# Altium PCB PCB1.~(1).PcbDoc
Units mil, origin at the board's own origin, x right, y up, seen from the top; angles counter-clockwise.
Board outline 2362.2 x 2362.2 mil, 2 copper layers (Top Layer, Bottom Layer); 62 components, 63 nets, 221 pads, 155 vias.
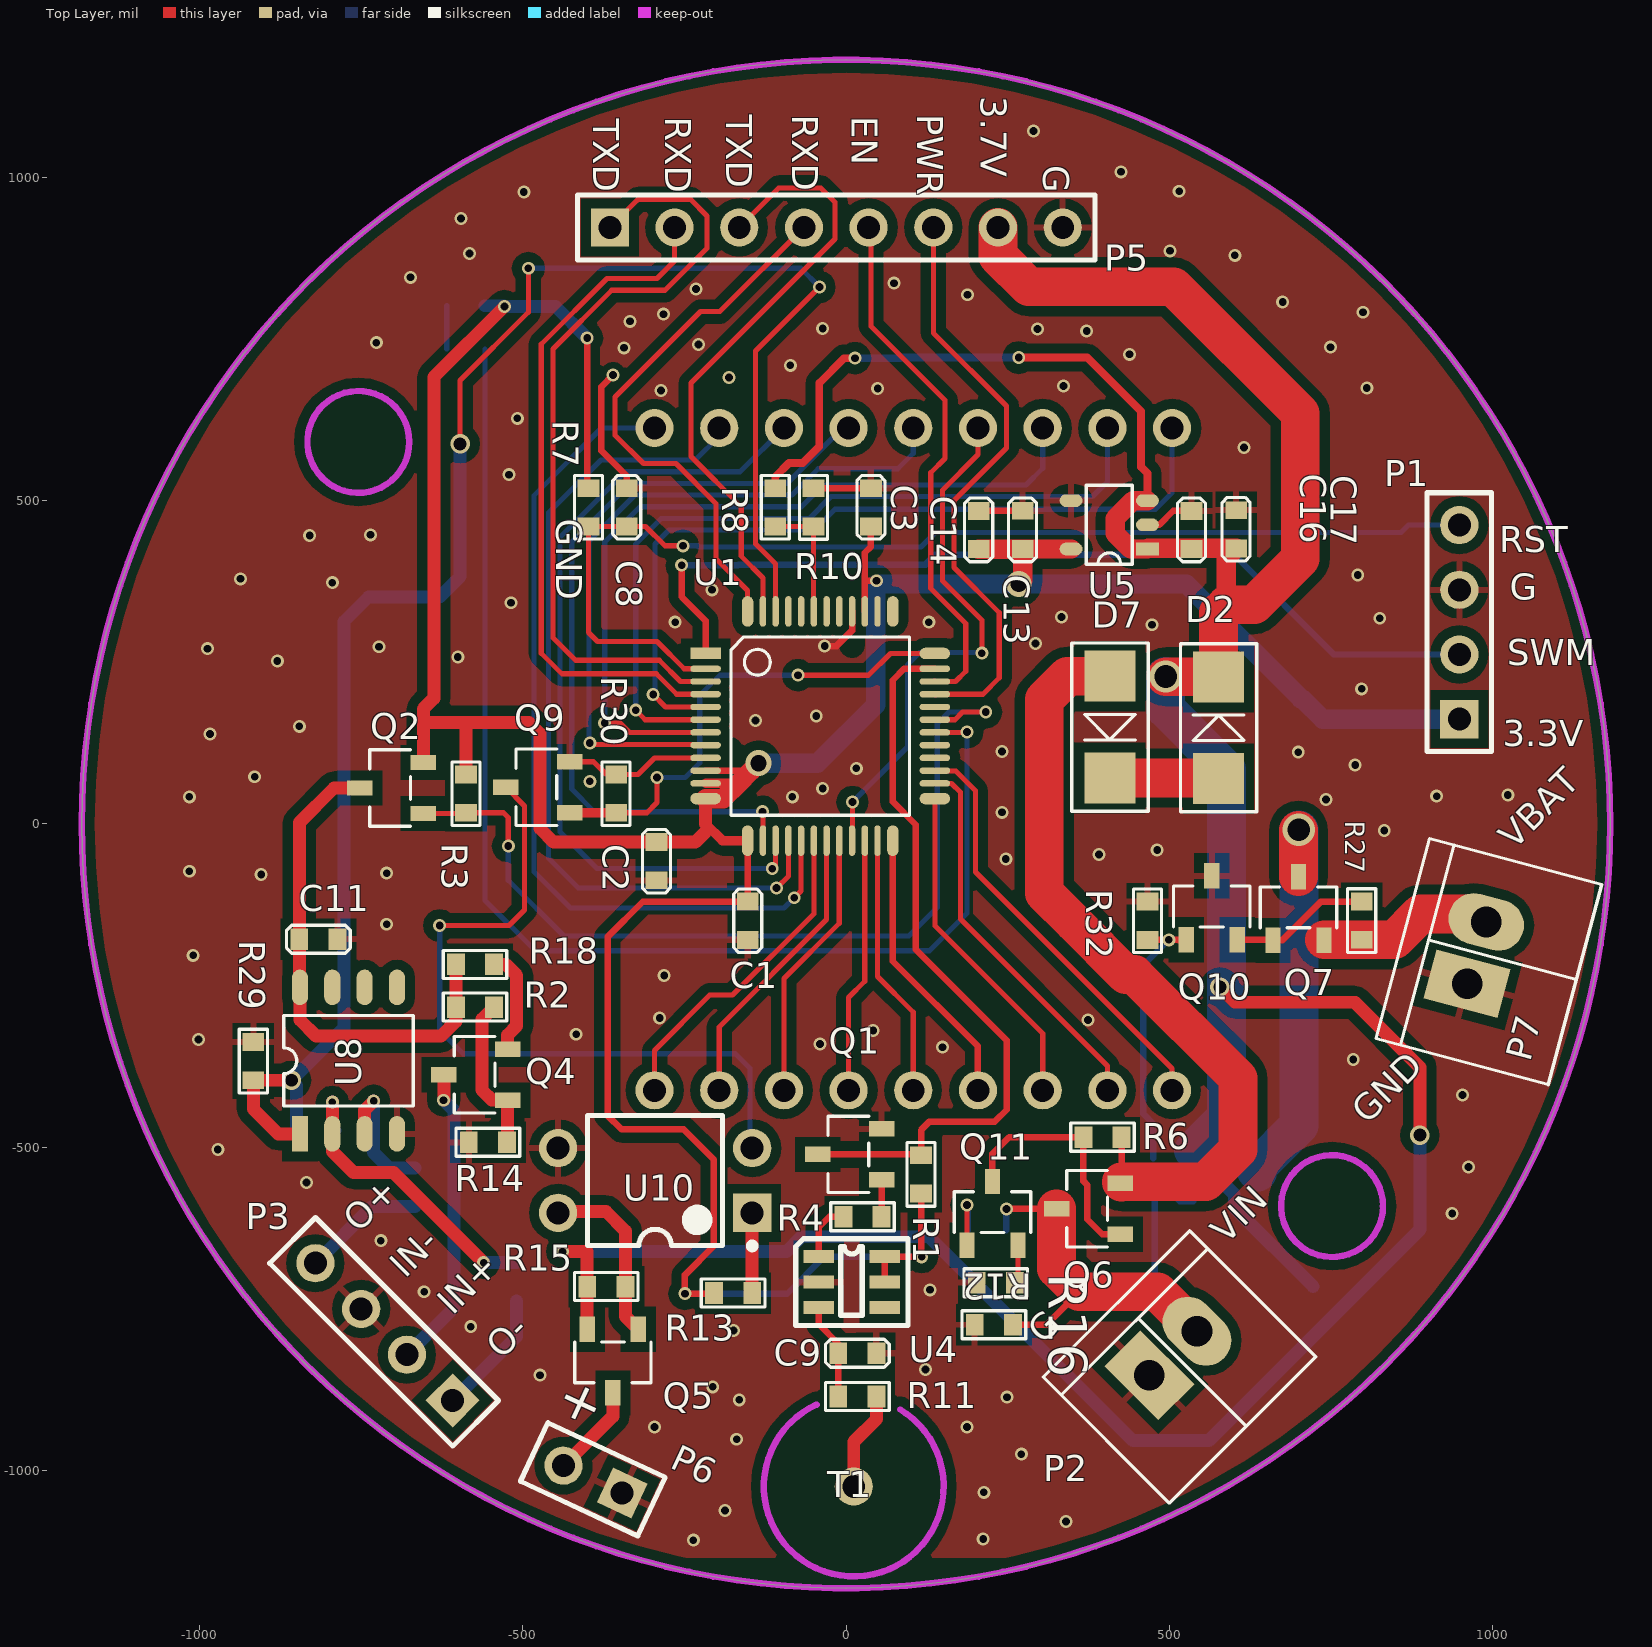
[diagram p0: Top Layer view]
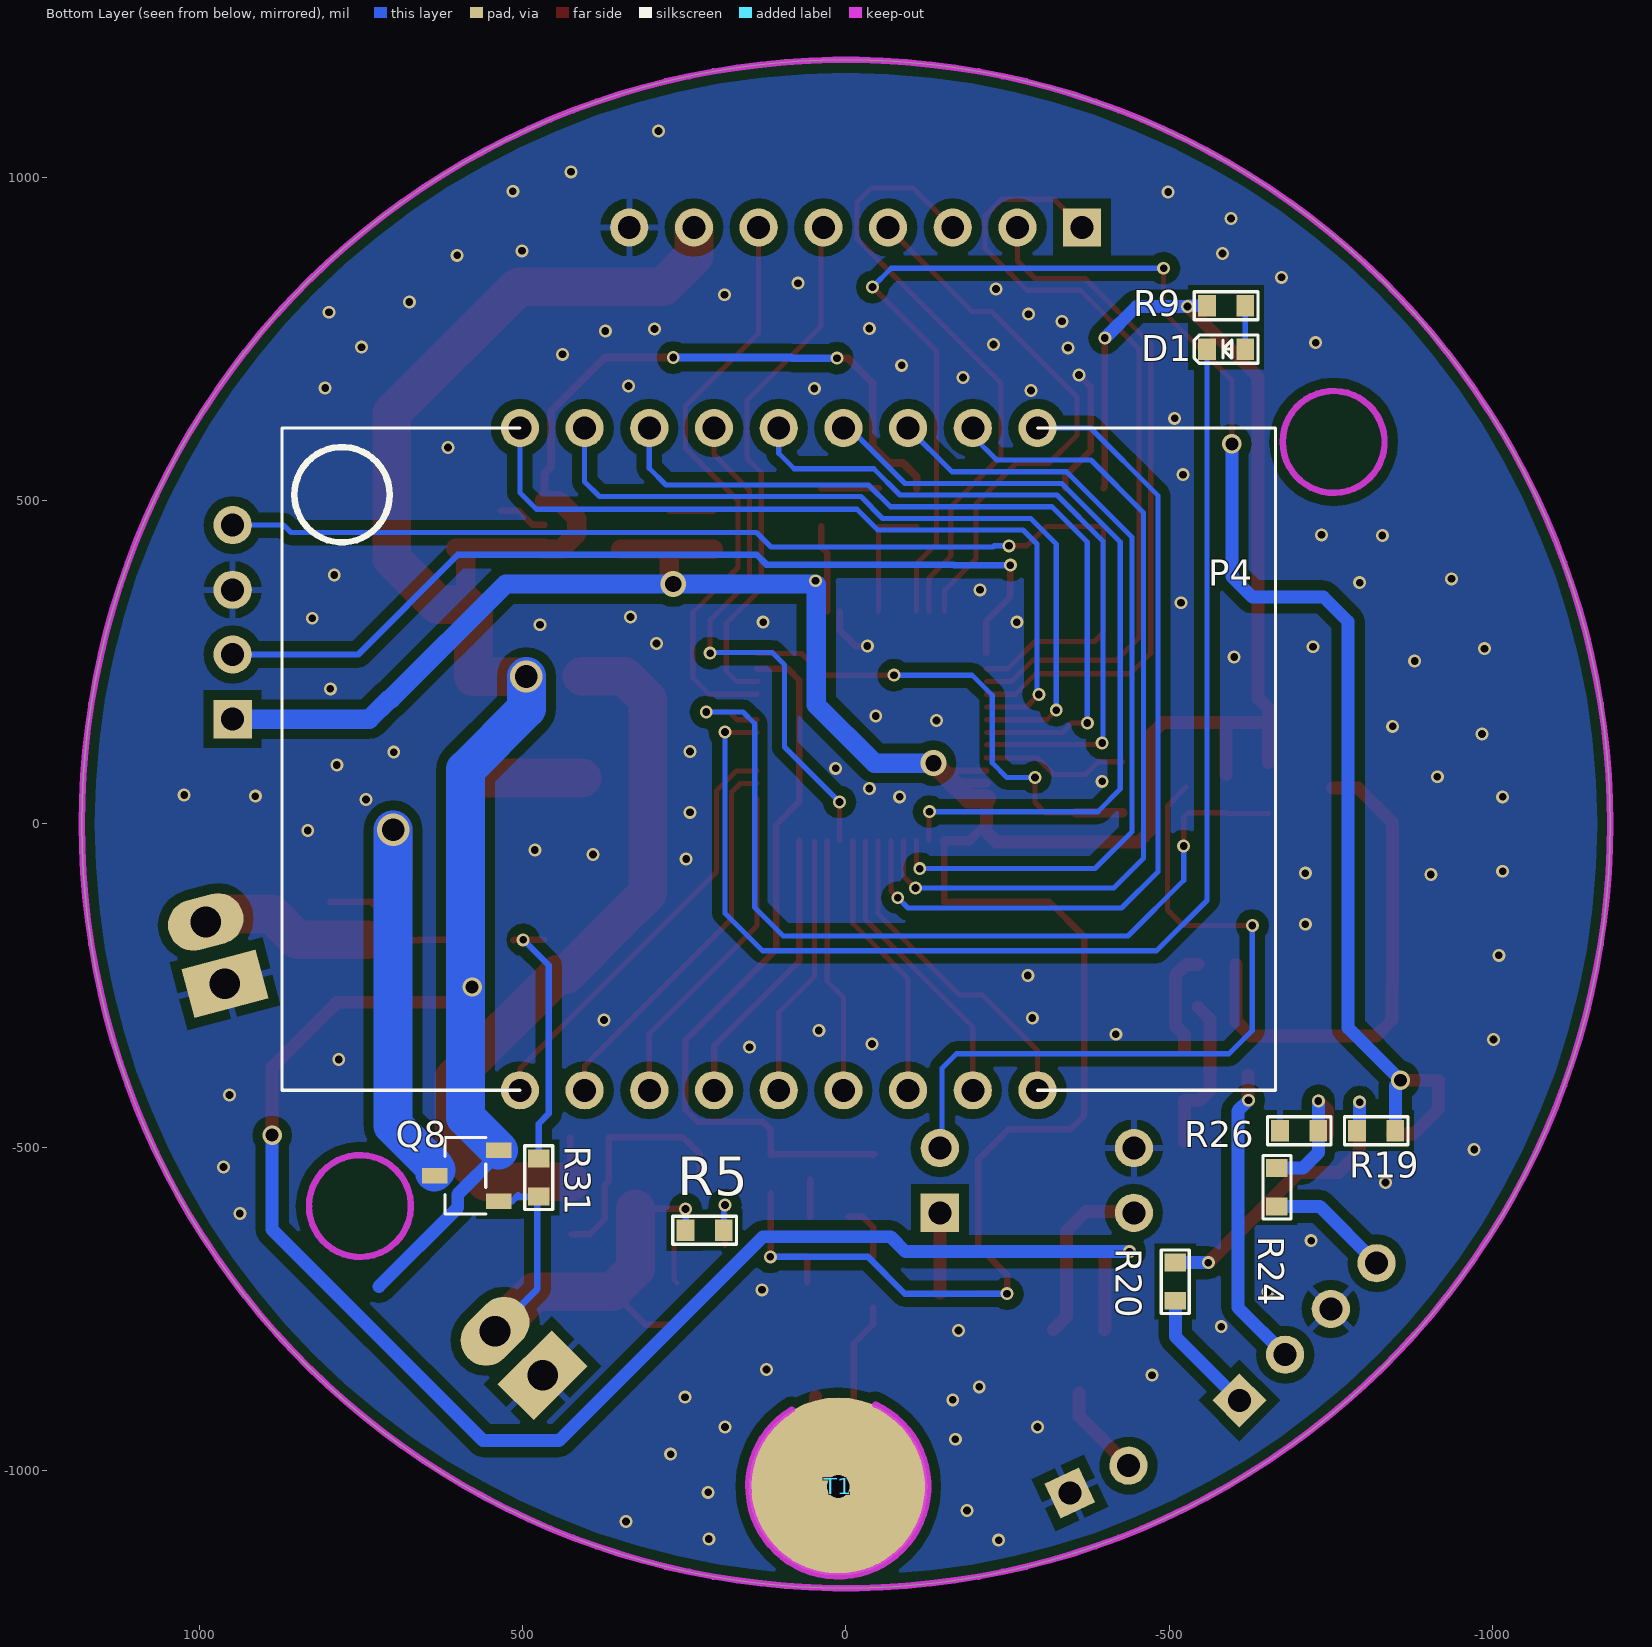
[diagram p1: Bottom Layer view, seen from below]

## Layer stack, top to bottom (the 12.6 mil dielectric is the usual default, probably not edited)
Top Layer: signal copper 1.4
Dielectric: core 12.6, FR-4, Dk 4.8
Bottom Layer: signal copper 1.4

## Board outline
-1181.1,0 ccw(c0,0) 0,-1181.1 ccw(c0,0) 1181.1,0 ccw(c0,0) 0,1181.1 ccw(c0,0)

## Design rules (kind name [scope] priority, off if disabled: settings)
Clearance Clearance_1 [InPolygon And InNet(GND)] p1: gap=15
Clearance [All] p2: gap=10
PolygonConnect PolygonConnect_1 [IsVia] p1: connectstyle=Direct reliefconductorwidth=10 reliefentries=4 polygonreliefangle="90 Angle"
PolygonConnect [All] p2: connectstyle=Relief reliefconductorwidth=10 reliefentries=4 polygonreliefangle="90 Angle"
RoutingVias [All] p1: holewidth=28 width=50 viastyle="Through Hole" minholewidth=28 minwidth=50 maxholewidth=28 maxwidth=50
SilkscreenOverComponentPads [All] p1: minsilkscreentomaskgap=10
SolderMaskExpansion [All] p1: expansion=4
Width [All] p1: maxlimit=200 minlimit=8 preferedwidth=10
27 further rules are at their usual default settings.

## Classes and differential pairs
component class MCU: C1 C2 C3 C8 C9 D1 P1 P4 P5 Q1 R1 R4 R7 R8 R9 R10 R11 T1 U1 U4
component class power: C11 C13 C14 C16 C17 D2 D7 P2 P3 P6 P7 Q2 Q4 Q5 Q6 Q7 Q8 Q9 Q10 Q11 R2 R3 R5 R6 R12 R13 R14 R15 R16 R18 R19 R20 R24 R26 R27 R29 R30 R31 R32 U5 U8 U10

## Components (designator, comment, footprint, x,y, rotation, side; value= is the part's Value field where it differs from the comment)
C1 "1uF/10V" 0603C -152,-120 r270 top
C2 "0.1uF/10V" 0603C -293,-28 r270 top
C3 "0.1uF/10V" 0603C 38.53,460 r90 top
C8 "0.1uF/10V" 0603C -339,460 r90 top
C9 "47pF/10V" 0603C -12,-818 r0 top
C11 "0.1uF/10V" 0603C -845,-178 r0 top
C13 "0.1uF/10V" 0603C 273,425 r90 top
C14 "10uF/10V" 0603C 205,484 r270 top
C16 "10uF/10V" 0603C 534,484 r270 top
C17 "0.1uF/10V" 0603C 603,426 r90 top
D1 "LED0" 0603LED -617,734 r0 bottom
D2 "SS16" SMA 576,70 r90 top
D7 "SS16" SMA 408,228.42 r270 top
P1 "Header 4" HDR1X4 948,162 r90 top
P2 "Header 2" 2X2.54MM 469,-852 r45 top
P3 "Header 4" HDR1X4 -608,-891 r135 top
P4 "Header 18" LCD 504,612 r180 bottom
P5 "Header 8" HDR1X8 -365,922 r0 top
P6 "Header 2" HDR1X2 -346,-1034 r155 top
P7 "Header 2" 2X2.54MM 960,-247 r75 top
Q1 "S8050" SOT23-3 55,-550 r0 top
Q2 "Si2369DS" SOT23-3 -653.32,16.35 r0 top
Q4 "MMBT9015" SOT23-3 -523,-427 r0 top
Q5 "Si2369DS" SOT23-3 -321,-781 r90 top
Q6 "Si2369DS" SOT23-3 424,-634 r0 top
Q7 "Si2369DS" SOT23-3 660,-180 r270 top
Q8 "Si2369DS" SOT23-3 537,-583 r180 bottom
Q9 "S8050" SOT23-3 -427.32,17.35 r0 top
Q10 "MMBT9015" SOT23-3 526,-178.69 r270 top
Q11 "S8050" SOT23-3 187,-651 r270 top
R1 "100" 0603R 116,-571 r90 top
R2 "10K" 0603R -603,-283 r0 top
R3 "10K" 0603R -587.32,76.35 r270 top
R4 "1K" 0603R -4,-607 r0 top
R5 "100K" 0603R 248,-628 r180 bottom
R6 "10K" 0603R 426,-484 r180 top
R7 "10K" 0603R -398,460 r90 top
R8 "100K" 0603R -109.35,460 r90 top
R9 "1K" 0603R -558,801 r180 bottom
R10 "100K" 0603R -50.35,519 r270 top
R11 "1K" 0603R -12,-885 r0 top
R12 "100K" 0603R 258,-774 r180 top
R13 "100" 0603R -145,-725 r180 top
R14 "10K" 0603R -524,-492 r180 top
R15 "10K" 0603R -341,-715 r180 top
R16 "10K" 0603R 202,-709 r0 top
R18 "330/1%" 0603R -603,-217 r0 top
R19 "100K" 0603R -790,-474 r180 bottom
R20 "2.2K" 0603R -509,-737 r90 bottom
R24 "2.2K" 0603R -666,-591 r90 bottom
R26 "100K" 0603R -671,-474 r180 bottom
R27 "100K" 0603R 797,-179 r90 top
R29 "100K" 0603R -916,-337 r270 top
R30 "10K" 0603R -355.32,76.35 r270 top
R31 "1K" 0603R 475,-576 r90 bottom
R32 "100K" 0603R 466,-120 r270 top
T1 "TP" TOUCH-PAD 12,-1024 r0 top
U1 "STM8L152C6T6" TQFP-48 -217,240 r0 top
U4 "RH6030" SOT-23-6 9,-708 r0 top
U5 "TLV70230DBVR" SOT23-5(DBV) 466,425 r180 top
U8 "LM258" so-8 -844,-479 r90 top
U10 "TL181" DIP-4 -295,-551 r180 top

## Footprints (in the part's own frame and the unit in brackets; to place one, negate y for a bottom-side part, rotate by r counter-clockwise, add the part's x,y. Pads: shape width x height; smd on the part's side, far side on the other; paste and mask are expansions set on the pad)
2X2.54MM [mm]
  rect 2x3 hole 1.2: 1(0,0)
  oval 2x3 hole 1.2: 2(2.54,-0.1)
  silkscreen extent -3,-4.1 5.13,2.9
0603C [mm]
  rect 0.7x0.85 smd: 1(0,0) 2(1.5,0)
  silkscreen extent -0.5,-0.55 2,0.55
0603LED [mm]
  rect 0.7x0.85 smd: 1(0,0) 2(1.5,0)
  silkscreen extent -0.5,-0.55 2,0.55
0603R [mm]
  rect 0.7x0.85 smd: 1(0,0) 2(1.5,0)
  silkscreen extent -0.5,-0.55 2,0.55
DIP-4 [mm] "DIP; 4 Leads; Row Spacing 7.62 mm; Pitch 2.54 mm"
  rect 1.5x1.5 hole 0.9: 1(-3.81,1.27)
  round 1.5 hole 0.9: 2(-3.81,-1.27) 3(3.81,-1.27) 4(3.81,1.27)
  silkscreen extent -3.94,-2.55 2.65,2.69, body extent -3.15,-2.5 3.15,2.5, height 5.6
HDR1X2 [mm] "Connector; Header; 2 Position"
  rect 1.5x1.5 hole 0.9: 1(0,0)
  round 1.5 hole 0.9: 2(2.54,0)
  silkscreen extent -1.27,-1.27 3.81,1.27
HDR1X4 [mm]
  rect 1.5x1.5 hole 0.9: 1(0,0)
  round 1.5 hole 0.9: 2(2.54,0) 3(5.08,0) 4(7.62,0)
  silkscreen extent -1.27,-1.27 8.89,1.27
HDR1X8 [mm] "Connector; Header; 8 Position"
  rect 1.5x1.5 hole 0.9: 1(0,0)
  round 1.5 hole 0.9: 2(2.54,0) 3(5.08,0) 4(7.62,0) 5(10.16,0) 6(12.7,0) 7(15.24,0) 8(17.78,0)
  silkscreen extent -1.27,-1.27 19.05,1.27
LCD [mm]
  round 1.5 hole 0.9: 1(0,0) 2(2.54,0) 3(5.08,0) 4(7.62,0) 5(10.16,0) 6(12.7,0) 7(15.24,0) 8(17.78,0) 9(20.32,0) 10(20.32,-26) 11(17.78,-26) 12(15.24,-26) 13(12.7,-26) 14(10.16,-26) 15(7.62,-26) 16(5.08,-26) 17(2.54,-26) 18(0,-26)
  silkscreen extent -9.34,-26 29.66,0
SMA [mm]
  rect 2x2 smd: 1(0,0) 2(4,0)
  silkscreen extent -1.3,-1.5 5.3,1.5
so-8 [mil]
  rect 55x25 smd: 1(0,0)
  oval 55x25 smd: 2(0,-50) 3(0,-100) 4(0,-150) 5(226.38,-150) 6(226.38,-100) 7(226.38,-50) 8(226.38,0)
  silkscreen extent 43,-175 183,25
SOT23-3 [mm]
  rect 1x0.6 smd: 1(0,0) 2(0,2) 3(-2.5,1)
  silkscreen extent -2.1,-0.5 -0.5,2.5
SOT23-5(DBV) [mm]
  rect 0.9x0.5 smd: 1(0,0)
  oval 0.9x0.5 smd: 2(0,-0.95) 3(0,-1.9) 4(3,-1.9) 5(3,0)
  silkscreen extent 0.6,-2.5 2.4,0.6
SOT-23-6 [mm]
  rect 1.2x0.5 smd: 1(-1.3,1) 2(-1.3,0) 3(-1.3,-1) 4(1.3,-1) 5(1.3,0) 6(1.3,1)
  silkscreen extent -2.2,-1.7 2.2,1.7
TOUCH-PAD [mm]
  round 1.5 hole 0.9: 1(0,0)
  round 7 smd far side: ""(0,0)
TQFP-48 [mm]
  rect 1.2x0.45 smd: 1(0,0.6)
  oval 1.2x0.25 smd: 2(0,0) 3(0,-0.5) 4(0,-1) 5(0,-1.5) 6(0,-2) 7(0,-2.5) 8(0,-3) 9(0,-3.5) 10(0,-4) 11(0,-4.5) 26(9,-4.5) 27(9,-4) 28(9,-3.5) 29(9,-3) 30(9,-2.5) 31(9,-2) 32(9,-1.5) 33(9,-1) 34(9,-0.5) 35(9,0)
  oval 1.2x0.45 smd: 12(0,-5.1) 25(9,-5.1) 36(9,0.6)
  oval 0.45x1.2 smd: 13(1.65,-6.75) 24(7.35,-6.75) 37(7.35,2.25) 48(1.65,2.25)
  oval 0.25x1.2 smd: 14(2.25,-6.75) 15(2.75,-6.75) 16(3.25,-6.75) 17(3.75,-6.75) 18(4.25,-6.75) 19(4.75,-6.75) 20(5.25,-6.75) 21(5.75,-6.75) 22(6.25,-6.75) 23(6.75,-6.75) 38(6.75,2.25) 39(6.25,2.25) 40(5.75,2.25) 41(5.25,2.25) 42(4.75,2.25) 43(4.25,2.25) 44(3.75,2.25) 45(3.25,2.25) 46(2.75,2.25) 47(2.25,2.25)
  silkscreen extent 1,-5.75 8,1.25

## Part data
C1 C2 C3 C8 C9 C11 C13 C14 C16 C17: library part Cap, "Capacitor"
D1: "Typical INFRARED GaAs LED"
D2 D7: library part "Diode 1N4148", "High Conductance Fast Diode"
P1 P3: "Header, 4-Pin"
P2 P6 P7: "Header, 2-Pin"
P4: "Header, 18-Pin"
P5: "Header, 8-Pin"
Q1 Q9 Q11: library part NPN
Q2 Q5 Q6 Q7 Q8: library part BUK92150-55A, "BUK92150-55A"
Q4 Q10: library part PNP
R1 R4 R9 R11: library part Res2, "Resistor"
R2 R3 R5 R6 R7 R8 R10 R12 R13 R14 R15 R16 R18 R19 R20 R24 R26 R27 R29 R30 R31 R32: library part R, "R"
U10: library part Optoisolator1, "4-Pin Phototransistor Optocoupler"

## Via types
v1: diameter 20, hole 12, Top Layer to Bottom Layer, tented both sides, 147 vias
v2: diameter 30, hole 20, Top Layer to Bottom Layer, tented both sides, 4 vias
v3: diameter 50, hole 35, Top Layer to Bottom Layer, tented both sides, 2 vias
v4: diameter 40, hole 25, Top Layer to Bottom Layer, tented both sides, 2 vias

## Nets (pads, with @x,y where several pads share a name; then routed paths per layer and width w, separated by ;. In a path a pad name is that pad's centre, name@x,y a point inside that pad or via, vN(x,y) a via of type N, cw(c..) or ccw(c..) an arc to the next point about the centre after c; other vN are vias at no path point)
FLOW: Q9.1 R30.2 U1.36 | length 750.7
  Top Layer w8: R30.2 -307.71,17.29 -292,33 v1(-292,72) ; v1(-74,230) 35,230 68.62,263.62 U1.36
  Top Layer w15: Q9.1 -355.37,17.35 R30.2
  Bottom Layer w8: v1(-292,72) -248.6,72 -226,94.6 -226,199 -195,230 v1(-74,230)
GND: C1.2 C2.2 C3.2 C8.2 C9.2 C11.2 C13.2 C14.1 C16.1 C17.2 P1.3 P2.1 P3.3 P5.8 P6.1 P7.1 Q1.2 Q9.2 Q10.3 R10.1 R12.2 R14.2 R16.1 R26.1 R29.1 R30.1 R32.1 U1.9 U1.40 U4.2 U5.2 U5.4 U8.4 U10.3 | length 801.2
  Top Layer w8: Q9.2 -390.09,96.09 -370.35,76.35 R30.1 -321.65,76.35 -295.8,102.2 U1.9 ; -273.55,102.2 U1.9 ; U1.9@-216.24,102.97 U1.9
  Top Layer w10: v1(-360,694) -378,676 -378,577 -339,538 C8.2 ; R10.1 38.47,519 C3.2 ; v1(-33,275) -14.62,275 9.38,299 9.38,301.39 U1.40 ; C14.1 272.94,484 C13.2 ; U5.2 484.4,462.4 506,484 C16.1
  other v1: -236,-1107 212,-1105 340,-1078 -187,-1061 213,-1033 271,-974 -169,-951 -296,-932 187,-932 -165,-890 249,-886 -206,-870 -473,-852 123,-843 -174,-783 -580,-777 -652,-723 130,-720 -719,-644 937,-602 -834,-554 962,-530 -971,-503 953,-419 784,-364 149,-345 -40,-340 -1001,-333 -417,-325 42,-319 374,-303 -288,-300 -281,-234 -1009,-203 -710,-155 -904,-78 -710,-76 -1015,-73 247,-54 391,-47 481,-40 832,-10 241,18 742,38 -1015,42 -83,42 913,43 1023,45 -36,55 -396,66 -914,73 16,86 787,91 699,111 241,112 -983,139 -845,151 -140,160 -46,167 797,209 -879,252 -600,258 -987,271 -722,274 293,279 473,308 -264,312 128,312 825,318 333,320 -518,342 -207,362 -794,373 -936,379 791,385 -829,446 -735,447 -521,540 615,582 -508,627 -286,670 49,673 805,674 336,677 -181,690 -86,709 438,726 -343,736 749,737 -228,741 -726,744 372,762 296,765 -36,766 -334,777 -282,788 799,791 675,807 188,818 -232,827 74,836 -673,845 601,879 -582,882 501,886 -595,936 -498,977 515,978 425,1008 290,1071
GNSS_EN_IN: P5.5 U1.34 | length 821.6
  Top Layer w8: P5.5 38.53,918.47 38.53,769.47 153,655 153,565 131,543 131,364 185,310 185,236 169.31,220.31 U1.34 U1.34@136.57,221.08
LCD_COM0: P4.1 U1.5 | length 1254.9
  Top Layer w8: v1(-298,200) -278.94,180.94 U1.5
  Bottom Layer w8: v1(-298,200) -295,203 -295,433 -273.61,454.39 -49.11,454.39 -17,486.5 478.5,486.5 504,512 P4.1
LCD_COM1: P4.2 U1.6 | length 1222.9
  Top Layer w8: v1(-325,176) -310.26,161.26 U1.6
  Bottom Layer w8: v1(-325,176) -325,433 -285.61,472.39 -56.56,472.39 -22.96,506 381,506 404,529 P4.2
LCD_COM2: P4.3 U1.7 | length 1228.2
  Top Layer w8: v1(-373,156) -349,156 -334.57,141.57 U1.7
  Bottom Layer w8: v1(-373,156) -373,436 -318.61,490.39 -68.61,490.39 -35,524 278,524 304,550 P4.3
LCD_COM3: P4.4 U1.21 | length 826.5
  Top Layer w8: U1.21 10,-25.13 v1(10,34) ; P4.4 204,571 149,516 149,376 210,315 v1(210,264)
  Bottom Layer w8: v1(10,34) 95,119 95,246 114,265 209,265 v1(210,264)
LCD_SEG0: P4.5 U1.8 | length 1089.3
  Top Layer w8: v1(-396,125) -393.65,122.65 -217.76,122.65 U1.8
  Bottom Layer w8: v1(-396,125) -397,126 -397,437.46 -326.06,508.39 -83.61,508.39 -43,549 80,549 104,573 P4.5
LCD_SEG1: P4.6 U1.14 | length 1236.5
  Top Layer w8: U1.14 v1@-128.42,18.42
  Bottom Layer w8: v1(-129,19) -389,19 -424,54 -424,423 -424,435.91 -333.52,526.39 -91.06,526.39 -5.46,612 P4.6
LCD_SEG2: P4.7 U1.15 | length 1268.3
  Top Layer w8: v1(-114,-69) -114,-68 -108.73,-62.73 U1.15
  Bottom Layer w8: v1(-114,-69) -385,-69 -442,-12 -442,443.37 -340.97,544.39 -163.61,544.39 P4.7
LCD_SEG3: P4.8 U1.16 | length 1318
  Top Layer w8: v1@-101.57,-99 v1(-107.43,-99) -89.05,-80.62 U1.16
  Bottom Layer w8: P4.8 -196,599.39 -233,562.39 -326,562.39 -378.61,562.39 -460,481 -460,-53 -414,-99 v1(-107.43,-99)
LCD_SEG4: P4.9 U1.17 | length 1335.6
  Top Layer w8: v1(-80,-114) -69.36,-103.36 U1.17
  Bottom Layer w8: P4.9 -378,612 -482,508 -482,-74 -426,-130 -96,-130 v1(-80,-114)
LCD_SEG5: P4.10 U1.18 | length 508.4
  Top Layer w8: P4.10 -296,-350 -210.5,-264.5 -175.5,-264.5 -49.68,-138.68 U1.18
LCD_SEG6: P4.11 U1.19 | length 454.6
  Top Layer w8: P4.11 -196,-313.54 -29.99,-147.54 U1.19
LCD_SEG7: P4.12 U1.20 | length 421.4
  Top Layer w8: P4.12 -96,-239 -10.31,-153.31 U1.20
LCD_SEG8: P4.13 U1.22 | length 396.3
  Top Layer w8: P4.13 4,-268 29.06,-242.94 U1.22
LCD_SEG9: P4.14 U1.23 | length 408.8
  Top Layer w8: U1.23 48.75,-235.75 104,-291 P4.14
LCD_SEG10: P4.15 U1.24 | length 440.4
  Top Layer w10: U1.24 72.37,-212 204,-343.63 P4.15
LCD_SEG11: P4.16 U1.25 | length 519.9
  Top Layer w8: U1.25 137.33,-157.33 304,-324 P4.16
LCD_SEG12: P4.17 U1.26 | length 600
  Top Layer w8: U1.26 163.17,62.83 177,49 177,-147 404,-374 P4.17
LCD_SEG13: P4.18 U1.27 | length 664.5
  Top Layer w8: U1.27 138.1,81.75 169.7,81.75 200,51.46 200,-74 504,-378 P4.18
NetC9_1: C9.1 R11.1 U4.3 | length 150.1
  Top Layer w10: U4.3 -42.18,-773 -12,-803.18 C9.1 R11.1
NetD1_1: D1.1 R9.2 | length 67
  Bottom Layer w8: R9.2 -617.06,734.06 D1.1
NetD1_2: D1.2 U1.30 | length 1983.2
  Top Layer w8: U1.30 186.57,141.57 v1(187,142)
  Bottom Layer w8: D1.2 -557.94,-118.06 -480,-196 129,-196 187,-138 v1(187,142)
NetD2_1: D2.1 D7.2 | length 168.4
  Top Layer w60: D7.2 575.06,70.94 D2.1
NetD7_1: D7.1 Q6.2 R6.1 | length 1216.5
  Top Layer w10: Q6.2 426,-553.26 R6.1
  Top Layer w60: D7.1 342.43,228.42 306.5,192.5 306.5,-106.64 351.93,-152.07 432.7,-232.83 445.83,-232.83 606,-393 606,-503 556,-553 426.26,-553 Q6.2@426,-553.26
NetP6_2: P6.2 Q5.3 | length 143.9
  Top Layer w20: P6.2 -360.37,-915.48 Q5.3
NetQ1_1: Q1.1 R4.2 | length 57
  Top Layer w10: Q1.1 55,-606.94 R4.2
NetQ4_1: Q4.1 R2.2 R14.1 | length 246.3
  Top Layer w20: R2.2 -562.69,-301.74 -562.69,-411.31 -547,-427 Q4.1 R14.1@-523,-491
NetQ4_2: Q4.2 R18.2 | length 162
  Top Layer w20: R18.2 -526,-217 -509,-234 -509,-312 -523,-326 Q4.2
NetQ5_1: Q5.1 R15.1 U10.4 | length 277.5
  Top Layer w20: U10.4 -443,-599 -371,-599 -341,-629 R15.1 -341,-761 Q5.1
NetQ6_1: Q6.1 Q11.3 R6.2 | length 384.2
  Top Layer w10: Q11.3 226.37,-509.63 252,-484 R6.2 366.94,-551.94 373,-558 373,-611 396,-634 Q6.1
NetQ7_1: Q7.1 Q10.2 R27.2 | length 217.7
  Top Layer w10: Q10.2 658.69,-178.69 Q7.1 674,-180 734.06,-119.94 R27.2
NetQ7_3: Q7.3 Q8.3 | length 631.5
  Top Layer w60: Q7.3 v3@699.37,-9.63
  Bottom Layer w60: Q8.3@633.43,-535.03 636.39,-537.99 636.39,-529.58 700,-465.97 v3(700,-9)
NetQ9_3: Q9.3 U10.2 | length 1133.2
  Top Layer w8: v1(-628,-157) -521,-157 -497,-133 -497,27.98 Q9.3
  Bottom Layer w8: v1(-628,-157) -628,-319 -592,-355 -171,-355 -148.53,-377.47 -148.53,-497.47 U10.2
NetQ10_1: Q10.1 R31.2 R32.2 | length 409.1
  Top Layer w10: R32.2 513.06,-179.06 514,-180
  Bottom Layer w10: R31.2 475,-463.12 459.47,-447.59 459.47,-218.53 v1(499,-179)
NetQ11_1: Q11.1 R5.2 | length 101.8
  Top Layer w8: Q11.1 v1(187,-589)
  Bottom Layer w8: v1(187,-589) 188.94,-590.94 R5.2
NetQ11_2: Q11.2 R16.2 | length 59.9
  Top Layer w8: R16.2 265.74,-704.31 Q11.2
NetR4_1: R4.1 U4.1 | length 90.3
  Top Layer w10: U4.1 -42.18,-623.18 -26,-607 R4.1
NetR11_2: R11.2 T1.1 | length 153.5
  Top Layer w20: T1.1 12,-955 47.06,-919.94 R11.2
NetR13_1: R13.1 U10.1 | length 124
  Top Layer w20: R13.1 U10.1
NetR19_1: R19.1 R20.2 U8.2 | length 477.8
  Top Layer w20: v1(-794,-430) U8.2 -794,-506 -761,-539 -699,-539 v1(-560,-678)
  Bottom Layer w20: v1(-794,-430) -794,-470 R19.1 ; v1@-559.94,-677.94 R20.2
NetR24_2: R24.2 R26.2 U8.3 | length 210.6
  Top Layer w20: U8.3 -744,-442 v1(-730.06,-428.06)
  Bottom Layer w20: v1(-730.06,-428.06) R26.2 -730.06,-507.94 -706.06,-531.94 R24.2
OUT+: P3.4 R24.1 | length 198.5
  Bottom Layer w20: P3.4@-820.13,-670.87 P3.4 -732.26,-591 R24.1
OUT-: P3.1 R20.1 | length 195
  Bottom Layer w20: P3.1 -509,-792 R20.1
P1: P3.2 Q4.3 | length 469.1
  Top Layer w20: v1@-621.43,-426.43 Q4.3
  Bottom Layer w20: P3.2 -605.71,-747.29 -605.71,-443.29 v1(-622,-427)
POWER: U1.41
PWRKEY_IN: P5.6 U1.33 | length 921.6
  Top Layer w8: U1.33@138.1,199.87 U1.33 211.63,200.63 237,226 237,326.53 167,396.53 167,500 248,581 248,646 135,759 P5.6 P5.6@138.53,918.47
RST: C8.1 P1.4 R7.1 U1.2 | length 1746.8
  Top Layer w8: v1@-255,427 v1(-252,430) -280,430 -310,460 C8.1 R7.1 -398,296 -384,282 -292.09,282 -250.09,240 U1.2
  Bottom Layer w8: v1(-252,430) -230,430 ; -229,430 -230,430 ; P1.4 869.5,462 858,450.5 138.5,450.5 116,428 -228,428 -230,430
SENSOR_EN: Q2.1 R3.2 U1.31 | length 1398.6
  Top Layer w8: Q2.1 -588.26,16.35 R3.2 -529.29,17.29 -522,10 v1(-522,-34) ; U1.31 168.26,161.26 180,173 v1(216,173)
  Bottom Layer w8: v1(-522,-34) -522,-87 -436,-173 97,-173 141,-129 141,155 159,173 v1(216,173)
SENSOR_OUT: R19.2 R29.2 U1.46 U8.1 | length 2749.9
  Top Layer w8: v2(-596.4,587.6) -596.4,660.6 -596.4,685.6 -491,791 v1(-491,859) ; U1.46 -108.73,401.73 -140.08,433.08 -140.08,538.63 -140,538.71 -140,731 v1(-41,830)
  Top Layer w20: v2(-857.06,-396.06) R29.2 -916,-440.54 -877.54,-479 U8.1
  Bottom Layer w8: v1(-491,859) -70,859 v1(-41,830)
  Bottom Layer w20: v2(-857.06,-396.06) -776,-315 -776,313 -738,351 -628,351 -596.4,382.6 v2(-596.4,587.6) ; R19.2 v2@-849.06,-404.06
SIM800_VBAT: C16.2 C17.1 D2.2 P5.7 Q5.2 Q8.2 R8.2 R15.2 U5.1 U5.3 | length 5893.2
  Top Layer w12: R8.2 -109.35,536.65 -88,558 -67,558 -41.53,583.47 -41.53,681.47 -3,720 v1(14,720) ; v1(267,721) 373,721 456,638 456,552 466,542 U5.3
  Top Layer w20: v1(-438,-661) -400.06,-661 R15.2 R15.2@-400.06,-718.69 ; Q5.2 -400.06,-780.69 R15.2@-400.06,-718.69 ; R15.2@-399.74,-719 R15.2@-400.06,-718.69 ; v2(578,-252) 601.5,-275.5 786.5,-275.5 887,-376 v2(887,-481)
  Top Layer w30: U5.3 443.8,499.8 416,472 416,449 440,425 U5.1 467,426 C17.1 588,411 588,339
  Top Layer w60: P5.7 235,878 282.52,830.48 506.26,830.48 702,634.74 702,410 631,339 588,339 ; v3@494.52,227.48 D2.2 576,327
  Bottom Layer w12: v1(14,720) 84,720 85,721 233,721 ; 247,721 233,721 ; v1(267,721) 233,721
  Bottom Layer w20: v1(-438,-661) -92,-661 -69,-638 128.43,-638 443.65,-953.22 560.78,-953.22 887,-627 v2(887,-481) ; Q8.2 537,-509.31 600.07,-572.38 600.07,-593.07 722,-715
  Bottom Layer w60: v3(494,228) 494,178 588,84 588,-453.26 Q8.2
SWIM: P1.2 U1.1 | length 1424.1
  Top Layer w10: v1(-254,400) -254,351 -217,314 U1.1
  Bottom Layer w10: v1(-254,400) -167,400 -166,401 123,401 138,416 600,416 754,262 P1.2
TOUCH: Q1.3 R1.2 U1.35 | length 1156.2
  Top Layer w10: Q1.3@-43,-510.2 Q1.3 ; Q1.3@-42.11,-511.94 Q1.3 ; U1.35 90.47,240 90.24,240.24 72.37,222.37 72.37,34.63 108,-1 108,-194 248.53,-334.53 248.53,-441.47 230,-460 129,-460 116,-473 R1.2 114.69,-510.63 Q1.3
UART1_RXD: P5.2 U1.4 | length 1068.9
  Top Layer w8: P5.2 -265,870 -292,843 -369.46,843 -471,741.46 -471,264 -439.22,232.22 -293.22,232.22 -261.63,200.63 U1.4
UART1_TXD: P5.1 U1.3 | length 1241.3
  Top Layer w8: P5.1 -322.14,964.86 -321.93,964.86 -321.27,965.53 -240.53,965.53 -215,940 -215,890 -280,825 -362,825 -453,734 -453,288 -418,253 -288.54,253 -255.86,220.31 U1.3
UART3_RXD: P5.4 U1.48 | length 846.2
  Top Layer w8: U1.48@-152,328.62 U1.48 -152.04,361.04 -201,410 -201,495 -263,557 -313,557 -357,601 -357,660 -225,792 -195,792 P5.4
UART3_TXD: P5.3 U1.47 | length 953
  Top Layer w8: P5.3 -104,983 -39,983 -17,961 -17,904 -239.53,681.47 -239.53,640 -239.53,568 -162,490.47 -162,414 -128.42,380.42 U1.47
VBAT_ADC: R8.1 R10.2 U1.43 | length 190.7
  Top Layer w8: R8.1 -50.4,460 R10.2 -50.35,329.25 U1.43
VBAT_IN: P7.2 Q7.2 R27.1 | length 271.7
  Top Layer w60: Q7.2@739.74,-179 R27.1 848,-179 888,-139 977.26,-139 P7.2
VCC_3V: C1.1 C2.1 C3.1 C13.1 C14.2 P1.1 Q2.2 R1.1 R3.1 R7.2 R9.1 R13.2 U1.10 U1.11 U1.12 U1.13 U1.39 U4.5 U4.6 U5.5 | length 5595
  Top Layer w10: v1(-400,751) -400,521.06 R7.2 ; U1.10@-217,82.28 v4@-146.72,82.28 ; R13.2 -205.06,-726 v1(-249,-726) -249,-697 -204.06,-652.06 -204.06,-519 -251.06,-472 -347,-472 -368.5,-450.5 -368.5,-174.5 -314,-120 C1.1 -152.04,-119.96 U1.13 ; U1.39 29.06,376 ; C3.1 38.53,428.53 29.06,419.06 29.06,376 ; v1(47,376) 29.06,376 ; U4.5 U4.6 115.37,-668.63 v1@116,-668 ; R1.1 v1@116,-668 ; v1(117,-669) v1@116,-668
  Top Layer w15: -217,0 -191.25,-25.75 U1.13 ; U1.11 -166.17,62.83
  Top Layer w20: Q2.2 -653.32,157 ; R3.1 -587.32,154.31 ; v1(-528,800) -637,691 -637,194.31 -653.32,178 -653.32,157 ; -217,-12 -233,-28 C2.1 -452,-28 -473,-7 -473,140 -490,157 -653.32,157 ; -217,0 U1.12
  Top Layer w30: U1.12 -189.79,39.21 -166.17,62.83 v4@-146.72,82.28 ; 241,424.94 C14.2 272.94,424.94 C13.1 ; v4@273,377 C13.1 ; U5.5 C13.1
  Bottom Layer w10: v1(-249,-726) -91,-726 -34,-669 v1(117,-669)
  Bottom Layer w20: R9.1 -529,801 v1(-528,800) -449,800 v1(-400,751)
  Bottom Layer w30: v4(-135,94) -44,94 46,184 v1@46,370 ; v1@52,371 v4(267,371) 526,371 703.19,193.81 ; 707.09,191.91 737,162 P1.1
VCC_3V_SENSOR: C11.1 Q2.3 R2.1 R18.1 U8.8 | length 769.8
  Top Layer w20: Q2.3 -791.28,55.72 -845,2 C11.1 -845,-251.62 U8.8 -844,-303 -819,-328 -626,-328 -603,-305 R2.1 R18.1
VCC_IN: P2.2 Q6.3 Q8.1 R5.1 R12.1 R31.1 | length 893.5
  Top Layer w10: v1@248,-594.63 Q6.3 ; R12.1 310,-774 361,-723
  Top Layer w60: Q6.3 325.57,-687.57 361,-723 481.42,-723 P2.2 P2.2@536,-777.58
  Bottom Layer w10: R5.1 v1(248,-595) ; Q8.1 516,-583 507,-574 505,-576 477,-576 477,-718.58 P2.2
pads on no net: T1. U1.28 U1.29 U1.32 U1.37 U1.38 U1.42 U1.44 U1.45 U4.4 U8.5 U8.6 U8.7

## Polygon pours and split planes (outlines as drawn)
GND on Top Layer "Top Layer-No Net" (solid, remove dead copper, pour order 1000): -1427.51,1342 -1377.51,1292 1010.49,1292 1010.49,919 1345.49,584 1339.49,578 1339.49,-388 1339.49,-515 922.49,-932 720.49,-1134 -865.51,-1134 -865.51,-931 -1389.51,-407 -1269.51,-287 -1269.51,1305
GND on Bottom Layer "Top Layer-No Net" (solid, remove dead copper, pour order 1001): -1442.33,1363.73 1440.67,1363.73 1440.67,-1131.27 1424.46,-1144.27 1306,-1239.27 -1151.78,-1239.27 -1151.78,-1137.27 -1387.46,-948.27 -1325.11,-898.27 -1325.11,1369.73

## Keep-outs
Keep-Out Layer:
  circle w10: c751.26,-590.55 r78.74
  circle w10: c-753.74,590.55 r78.74
  circle w10: c0,0 r1181.1
  lines w10: -45.38,-897.38 ccw(c12,-1024) 83.82,-904.98

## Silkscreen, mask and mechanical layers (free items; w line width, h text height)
Top Overlay:
  text "3.7V" at 208,1125 h40 r270
  text "PWR" at 110,1097 h40 r270
  text "TXD" at -185,1096 h40 r270
  text "RXD" at -83,1096 h40 r270
  text "EN" at 9,1094 h40 r270
  text "RXD" at -279,1093 h40 r270
  text "TXD" at -391,1090 h40 r270
  text "G" at 305,1018 h40 r270
  text "GND" at -448,472 h40 r270
  text "RST" at 1010,420 h40
  text "G" at 1026,347 h40
  text "SWM" at 1022,245 h40
  text "3.3V" at 1015,120 h40
  text "VBAT" at 1033,-41 h40 r45
  text "GND" at 806,-466 h40 r45
  text "O+" at -753,-633 h40 r45
  text "VIN" at 588,-651 h40 r45
  text "IN-" at -681,-704 h40 r45
  text "IN+" at -608,-761 h40 r45
  text "G" at 305,-806 h40 r45
  text "O-" at -532,-829 h40 r45
  text "+" at -368,-887 h60 r155
Mechanical 1:
  circle w10: c0,0 r1181.1
  circle w10: c-753.74,590.55 r78.74
  circle w10: c751.26,-590.55 r78.74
